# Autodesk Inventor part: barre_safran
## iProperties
Shininess: 64.0
Length Units: 11269
Angle Units: 11279
Time Units: 11290
Mass Units: 11283
Length Display Precision: 3
Angle Display Precision: 2
Compacted: True
Part Number: barre_safran
Document SubType Name: Modeling
Created: 2004-06
Material: Par défaut
Designer: David
Density: 0.0
Volumn: 0.0
Area: 0.0
PropertySet Name: Model Information
Control State: 0
Master: False
Checked Out: False
Author: David
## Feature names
1. Balayage1
2. Extrusion2
3. Chanfrein1 [Chamfer]
4. Perçage2 [Hole]
5. Extrusion4
6. Extrusion5
7. Extrusion6
